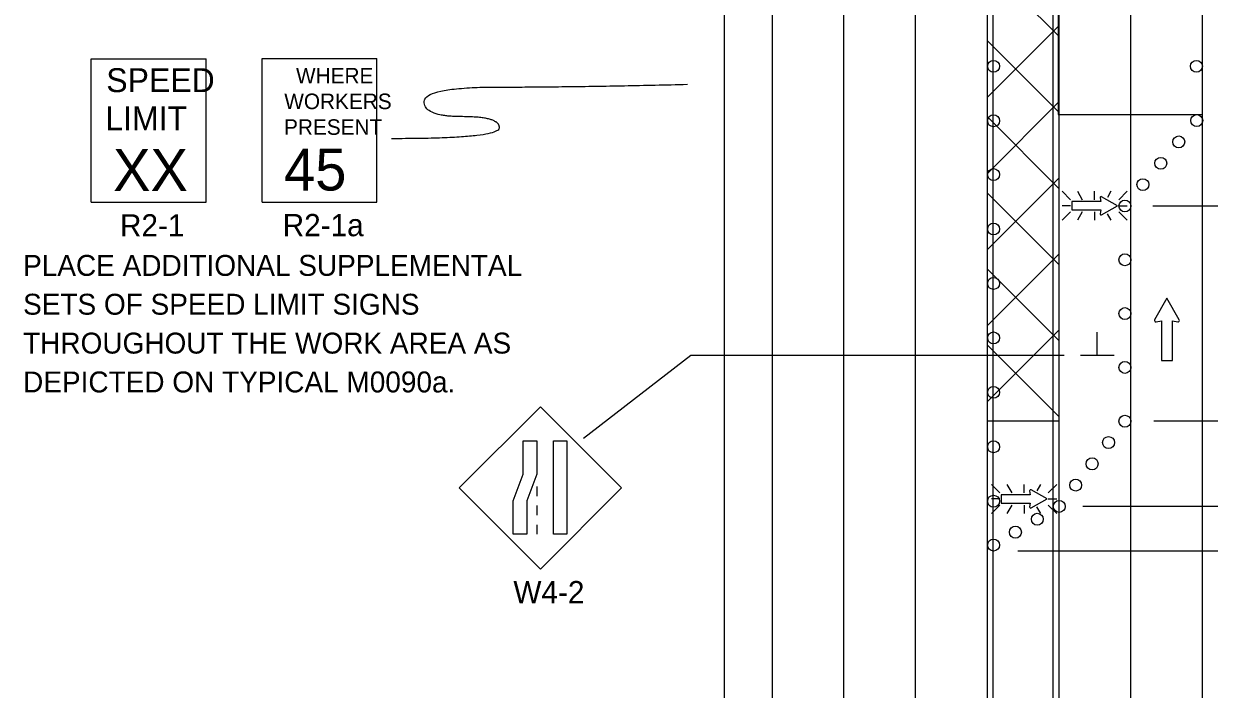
# Model space of a CAD drawing. Extents: x 16724 to 18475, y 5726 to 6929.
# Drawn here: x 16727 to 17123.6, y 6307.7 to 6530.4 of the extents above; entities that cross this region are included whole.
import ezdxf

# ---------------------------------------------------------------- set-up
doc = ezdxf.new("R2010")
doc.units = 0
for name, color, linetype in [('ALI_LEGAL_EX', 7, 'Continuous'), ('MT_SCRATCH_LEVEL_A', 7, 'Continuous'), ('MT_SCRATCH_LEVEL_E', 7, 'Continuous'), ('PAVT_EDGE_EX', 7, 'Continuous'), ('TRAFFIC_SIGNS_PR', 7, 'Continuous'), ('TYPICAL_TEXT_DIMEN_PR', 7, 'Continuous')]:
    doc.layers.add(name, color=color, linetype=linetype)

msp = doc.modelspace()

# ---------------------------------------------------------------- linework, layer by layer
at = {"layer": 'ALI_LEGAL_EX'}
for p, q in [((17001.36, 6131.68), (17001.36, 6928.96)), ((17025.36, 6131.68), (17025.36, 6928.96)), ((17051.36, 6131.68), (17051.36, 6928.96)), ((17071.36, 6131.68), (17071.36, 6928.96)), ((17097.36, 6131.68), (17097.36, 6928.96)), ((17121.36, 6131.68), (17121.36, 6928.96))]:
    msp.add_line(p, q, dxfattribs=at)
for points in [[(17001.36, 6431.68), (17001.36, 6456.68)], [(17025.36, 6431.68), (17025.36, 6456.68)], [(17051.36, 6431.68), (17051.36, 6456.68)], [(17071.36, 6431.68), (17071.36, 6456.68)], [(17121.36, 6431.68), (17121.36, 6456.68)], [(17001.36, 6331.68), (17001.36, 6356.68)], [(17025.36, 6331.68), (17025.36, 6356.68)], [(17051.36, 6331.68), (17051.36, 6356.68)], [(17071.36, 6331.68), (17071.36, 6356.68)], [(17097.36, 6331.68), (17097.36, 6356.68)], [(17121.36, 6331.68), (17121.36, 6356.68)]]:
    msp.add_lwpolyline(points, dxfattribs=at)
at = {"layer": 'MT_SCRATCH_LEVEL_A'}
for p, q in [((17073.36, 6526.21), (17049.36, 6550.21)), ((17049.36, 6505.66), (17073.36, 6529.66)), ((17073.36, 6500.75), (17049.36, 6524.75)), ((17049.36, 6480.2), (17073.36, 6504.2)), ((17073.36, 6475.29), (17049.36, 6499.29)), ((17049.36, 6454.75), (17073.36, 6478.75)), ((17073.36, 6449.84), (17049.36, 6473.84)), ((17049.36, 6429.29), (17073.36, 6453.29)), ((17073.36, 6424.38), (17049.36, 6448.38)), ((17049.36, 6403.83), (17073.36, 6427.83)), ((17073.36, 6398.93), (17049.36, 6422.93))]:
    msp.add_line(p, q, dxfattribs=at)
at = {"layer": 'MT_SCRATCH_LEVEL_E'}
for p, q in [((17109.46, 6438.6), (17105.35, 6431.36)), ((17109.46, 6438.6), (17105.35, 6431.36)), ((17113.61, 6431.36), (17109.46, 6438.6)), ((17113.61, 6431.36), (17109.46, 6438.6)), ((17105.83, 6430.67), (17107.61, 6430.99)), ((17105.83, 6430.67), (17107.61, 6430.99)), ((17107.61, 6430.99), (17107.61, 6417.73)), ((17107.61, 6430.99), (17107.61, 6417.73)), ((17111.35, 6417.73), (17111.35, 6430.99)), ((17111.35, 6430.99), (17113.13, 6430.67)), ((17111.35, 6417.73), (17111.35, 6430.99)), ((17111.35, 6430.99), (17113.13, 6430.67)), ((17107.61, 6417.73), (17111.35, 6417.73)), ((17107.61, 6417.73), (17111.35, 6417.73))]:
    msp.add_line(p, q, dxfattribs=at)
for centre, start, end in [((17105.76, 6431.13), 150.4248, 279.9638), ((17105.76, 6431.13), 150.4248, 279.9638), ((17113.2, 6431.13), 260.0362, 29.7731), ((17113.2, 6431.13), 260.0362, 29.7731)]:
    msp.add_arc(centre, 0.463, start, end, dxfattribs=at)
at = {"layer": 'PAVT_EDGE_EX'}
for p, q in [((16961.36, 6924.76), (16961.36, 6059.7)), ((16977.36, 6924.76), (16977.36, 6059.7)), ((17049.36, 6924.76), (17049.36, 6059.7)), ((17073.36, 6924.76), (17073.36, 6059.7))]:
    msp.add_line(p, q, dxfattribs=at)
msp.add_lwpolyline([(17121.36, 6579.99), (17073.11, 6579.99), (17073.11, 6499.97), (17121.36, 6499.97)], close=True, dxfattribs=at)
at = {"layer": 'TRAFFIC_SIGNS_PR'}
for p, q in [((16749.58, 6518.64), (16787.98, 6518.64)), ((16749.58, 6470.64), (16749.58, 6518.64)), ((16787.98, 6470.64), (16787.98, 6518.64)), ((16806.78, 6518.73), (16845.18, 6518.73)), ((16806.78, 6470.73), (16806.78, 6518.73)), ((16845.18, 6470.73), (16845.18, 6518.73)), ((17077.21, 6471.51), (17074.38, 6474.33)), ((17079.5, 6474.32), (17081.13, 6471.51)), ((17085.29, 6471.51), (17085.29, 6474.32)), ((17090.76, 6474.32), (17089.55, 6472.23)), ((17096.19, 6474.32), (17093.38, 6471.51)), ((16749.58, 6470.64), (16787.98, 6470.64)), ((16806.78, 6470.73), (16845.18, 6470.73)), ((17077.21, 6469.47), (17074.38, 6469.47)), ((17077.21, 6467.44), (17074.38, 6464.62)), ((17081.15, 6467.44), (17079.53, 6464.62)), ((17085.29, 6467.44), (17085.29, 6464.62)), ((17089.47, 6466.81), (17090.73, 6464.62)), ((17093.38, 6469.47), (17096.19, 6469.47)), ((17096.19, 6464.62), (17093.38, 6467.44)), ((16899.86, 6402.24), (16872.71, 6375.08)), ((16927.01, 6375.08), (16899.86, 6402.24)), ((16872.71, 6375.08), (16899.86, 6347.93)), ((16898.61, 6375.57), (16898.61, 6372.37)), ((16899.86, 6347.93), (16927.01, 6375.08)), ((17053.62, 6373.42), (17050.8, 6376.24)), ((17055.92, 6376.24), (17057.55, 6373.42)), ((17061.71, 6373.42), (17061.71, 6376.24)), ((17067.18, 6376.24), (17065.97, 6374.15)), ((17072.61, 6376.24), (17069.79, 6373.42)), ((17053.62, 6371.39), (17050.8, 6371.39)), ((17069.79, 6371.39), (17072.61, 6371.39)), ((16898.61, 6369.17), (16898.61, 6365.97)), ((17053.62, 6369.36), (17050.8, 6366.54)), ((17057.57, 6369.36), (17055.95, 6366.54)), ((17061.71, 6369.36), (17061.71, 6366.54)), ((17065.89, 6368.72), (17067.15, 6366.54)), ((17072.61, 6366.54), (17069.79, 6369.36)), ((16898.61, 6362.77), (16898.61, 6359.57))]:
    msp.add_line(p, q, dxfattribs=at)
for points in [[(17087.12, 6472.15), (17087.35, 6470.86), (17077.62, 6470.86), (17077.62, 6468.11), (17087.35, 6468.11), (17087.12, 6466.81)], [(17087.62, 6466.46), (17092.93, 6469.47), (17087.62, 6472.51)], [(17064.04, 6368.37), (17069.35, 6371.39), (17064.03, 6374.43)], [(17063.54, 6374.07), (17063.76, 6372.78), (17054.04, 6372.78), (17054.04, 6370.03), (17063.76, 6370.03), (17063.53, 6368.73)]]:
    msp.add_lwpolyline(points, dxfattribs=at)
for points in [[(16898.61, 6390.82), (16898.61, 6379.64), (16895.27, 6370.76), (16895.27, 6359.57), (16890.78, 6359.57), (16890.78, 6370.76), (16894.12, 6379.64), (16894.12, 6390.82)], [(16908.75, 6390.82), (16908.75, 6359.57), (16904.26, 6359.57), (16904.26, 6390.82)]]:
    msp.add_lwpolyline(points, close=True, dxfattribs=at)
for centre in [(17051.46, 6516.13), (17119.33, 6516.13), (17051.46, 6497.91), (17119.43, 6497.97), (17113.43, 6490.82), (17107.43, 6483.68), (17051.46, 6479.91), (17101.43, 6476.54), (17095.43, 6469.4), (17051.46, 6461.7), (17095.43, 6451.4), (17051.46, 6443.49), (17095.43, 6433.4), (17051.46, 6425.27), (17095.43, 6415.4), (17051.46, 6407.06), (17095.43, 6397.4), (17051.46, 6388.84), (17089.93, 6390.27), (17084.44, 6383.14), (17078.94, 6376.01), (17051.46, 6370.63), (17073.44, 6368.89), (17066.11, 6364.58), (17058.78, 6360.28), (17051.46, 6355.97)]:
    msp.add_circle(centre, 2, dxfattribs=at)
for centre, start, end in [((17087.45, 6472.21), 61.4833, 189.9593), ((17087.45, 6466.76), 170.7308, 298.8916), ((17063.87, 6374.13), 61.4833, 189.9593), ((17063.87, 6368.67), 170.7308, 298.8916)]:
    msp.add_arc(centre, 0.341, start, end, dxfattribs=at)
at = {"layer": 'TYPICAL_TEXT_DIMEN_PR'}
for p, q in [((17240.72, 6469.39), (17104.72, 6469.39)), ((17086.15, 6419.39), (17086.15, 6427.18)), ((16950.21, 6419.39), (16914.27, 6391.58)), ((17075.07, 6419.39), (16950.21, 6419.39)), ((17091.78, 6419.39), (17080.53, 6419.39)), ((17073.36, 6397.4), (17049.28, 6397.4)), ((17240.72, 6397.4), (17105.14, 6397.4)), ((17233.26, 6368.89), (17081.31, 6368.89)), ((17210.36, 6353.97), (17059.58, 6353.97))]:
    msp.add_line(p, q, dxfattribs=at)
msp.add_open_spline([(16850.06, 6492.02), (16886.15, 6492.02), (16886.15, 6499.29), (16860.98, 6499.29), (16860.98, 6509.19), (16910.62, 6509.19), (16949.03, 6510.11)], degree=2, dxfattribs=at)

# ---------------------------------------------------------------- texts
at = {"layer": 'TRAFFIC_SIGNS_PR'}
for s, height, p in [('SPEED', 8, (16754.61, 6507.5)), ('WHERE', 5.2, (16818.09, 6510.41)), ('WORKERS', 5.2, (16814.16, 6501.81)), ('LIMIT', 8, (16754.28, 6494.7)), ('PRESENT', 5.2, (16814.09, 6493.21)), ('XX', 14.031, (16756.89, 6474.4)), ('45', 14.031, (16814.08, 6474.58)), ('R2-1', 7.44, (16759.19, 6459.2)), ('R2-1a', 7.44, (16813.63, 6459.29)), ('PLACE ADDITIONAL SUPPLEMENTAL', 7, (16726.78, 6446.03)), ('SETS OF SPEED LIMIT SIGNS', 7, (16726.78, 6433.03)), ('THROUGHOUT THE WORK AREA AS', 7, (16726.78, 6420.03)), ('DEPICTED ON TYPICAL M0090a.', 7, (16726.78, 6407.03)), ('W4-2', 7.44, (16890.82, 6336.49))]:
    msp.add_text(s, height=height, dxfattribs=at).set_placement(p)

doc.saveas('drawing.dxf')
